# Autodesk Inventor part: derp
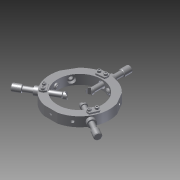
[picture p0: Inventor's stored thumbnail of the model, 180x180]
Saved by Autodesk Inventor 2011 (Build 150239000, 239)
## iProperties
Created: 2012-03
Part Number: derp
Document SubType Name: Modeling
Designer: vadybininkas6
Density: 1 g/cm^3
Author: vadybininkas6
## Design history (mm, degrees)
feature "Base1"
body "Solid1"
